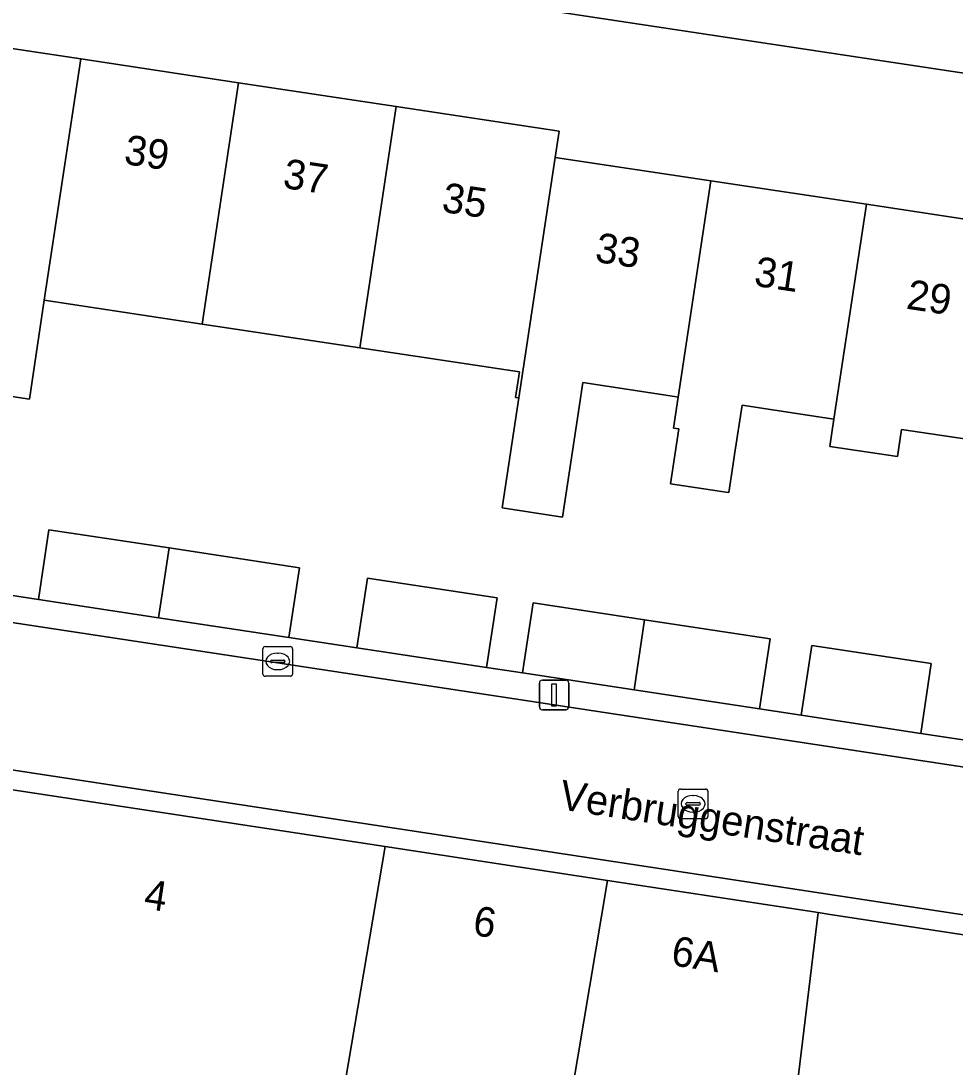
# Model space of a CAD drawing. Extents: x 163008 to 163854, y 382777 to 383982.
# Drawn here: x 163577.85 to 163609.33, y 383156.95 to 383192.22 of the extents above; entities that cross this region are included whole.
import ezdxf

# ---------------------------------------------------------------- set-up
doc = ezdxf.new("R2010")
doc.units = 0
for name, color, linetype in [('IMGEO_Erf', 7, 'Continuous'), ('IMGEO_Kolk', 7, 'Continuous'), ('IMGEO_Lichtmast', 7, 'Continuous'), ('IMGEO_Muur', 7, 'Continuous'), ('IMGEO_Openbare_ruimte_label', 7, 'Continuous'), ('IMGEO_Pand', 7, 'Continuous'), ('IMGEO_Pand_nummerreeks', 7, 'Continuous'), ('IMGEO_Rijbaan_lokaal_open', 7, 'Continuous'), ('IMGEO_Rioolput', 7, 'Continuous'), ('IMGEO_Voetpad_open', 7, 'Continuous')]:
    doc.layers.add(name, color=color, linetype=linetype)

msp = doc.modelspace()

# ---------------------------------------------------------------- linework, layer by layer
at = {"layer": 'IMGEO_Erf'}
for points in [[(163666.122, 383181.928), (163548.798, 383199.652), (163548.213, 383195.706), (163553.285, 383194.942), (163558.601, 383194.14), (163563.917, 383193.339), (163569.233, 383192.538), (163574.55, 383191.736), (163579.866, 383190.935), (163585.182, 383190.133), (163590.498, 383189.332), (163595.983, 383188.505), (163595.85, 383187.617), (163601.098, 383186.826), (163606.339, 383186.036), (163611.579, 383185.246)], [(163594.628, 383179.508), (163594.52, 383179.524), (163594.65, 383180.385), (163589.271, 383181.196), (163583.955, 383181.998), (163578.64, 383182.799), (163578.138, 383179.469), (163572.822, 383180.27), (163573.324, 383183.6), (163568.008, 383184.408), (163567.675, 383184.459), (163562.694, 383185.221), (163557.379, 383186.034), (163552.066, 383186.847), (163550.054, 383187.155), (163546.582, 383187.748), (163545.87, 383182.817), (163545.709, 383181.698), (163545.693, 383181.587)], [(163610.487, 383178.002), (163607.525, 383178.449), (163607.387, 383177.53), (163605.108, 383177.873), (163605.247, 383178.793), (163604.358, 383178.927), (163602.15, 383179.26), (163601.901, 383177.605), (163601.852, 383177.281), (163601.707, 383176.317), (163601.602, 383176.333), (163601.317, 383176.376), (163599.737, 383176.614), (163599.882, 383177.578), (163600.016, 383178.467), (163599.842, 383178.493), (163600, 383179.539), (163599.869, 383179.559), (163596.781, 383180.024), (163596.657, 383179.201), (163596.098, 383175.492), (163594.069, 383175.798), (163594.628, 383179.508)], [(163576.165, 383173.056), (163578.439, 383172.712), (163578.797, 383175.063), (163582.845, 383174.449), (163587.241, 383173.782), (163586.883, 383171.43), (163589.167, 383171.083), (163589.525, 383173.436), (163593.895, 383172.773), (163593.537, 383170.42), (163594.753, 383170.236), (163595.111, 383172.598), (163598.867, 383172.029), (163603.099, 383171.388), (163602.741, 383169.025), (163604.145, 383168.811), (163604.503, 383171.163), (163608.527, 383170.552), (163608.169, 383168.2), (163610.641, 383167.825)]]:
    msp.add_lwpolyline(points, dxfattribs=at)
at = {"layer": 'IMGEO_Kolk'}
for p, q in [((163586.005, 383170.201), (163586.005, 383171.053)), ((163586.08, 383171.127), (163586.932, 383171.127)), ((163586.493, 383170.907), (163586.518, 383170.907)), ((163587.006, 383171.053), (163587.006, 383170.201)), ((163586.264, 383170.621), (163586.264, 383170.633)), ((163586.702, 383170.584), (163586.304, 383170.584)), ((163586.307, 383170.67), (163586.705, 383170.67)), ((163586.748, 383170.633), (163586.748, 383170.621)), ((163586.932, 383170.127), (163586.08, 383170.127)), ((163586.516, 383170.347), (163586.491, 383170.347))]:
    msp.add_line(p, q, dxfattribs=at)
for points in [[(163586.005, 383170.201), (163586.005, 383171.053)], [(163586.08, 383171.127), (163586.932, 383171.127)], [(163587.006, 383171.053), (163587.006, 383170.201)], [(163586.932, 383170.127), (163586.08, 383170.127)]]:
    msp.add_lwpolyline(points, dxfattribs=at)
for centre, radius, start, end in [((163586.082, 383171.051), 0.0765, 91.552, 178.448), ((163586.082, 383171.051), 0.0765, 91.552, 178.448), ((163586.93, 383171.051), 0.0765, 1.552, 88.448), ((163586.93, 383171.051), 0.0765, 1.552, 88.448), ((163586.304, 383170.63), 0.0403, 85.8775, 175.7526), ((163586.301, 383170.62), 0.0366, 178.938, 274.7102), ((163586.705, 383170.627), 0.043, 264.8664, 352.4533), ((163586.709, 383170.632), 0.0386, 1.7309, 96.639), ((163586.082, 383170.203), 0.0765, 181.552, 268.448), ((163586.082, 383170.203), 0.0765, 181.552, 268.448), ((163586.93, 383170.203), 0.0765, 271.552, 358.448), ((163586.93, 383170.203), 0.0765, 271.552, 358.448)]:
    msp.add_arc(centre, radius, start, end, dxfattribs=at)
for centre, major_axis, ratio, start_param, end_param in [((163586.492, 383170.627), (-0.387, 0.002), 0.722429, 4.712389, 7.853982), ((163586.517, 383170.627), (-0.39, 0.002), 0.717154, 1.570796, 4.712389)]:
    msp.add_ellipse(centre, major_axis=major_axis, ratio=ratio, start_param=start_param, end_param=end_param, dxfattribs=at)
at = {"layer": 'IMGEO_Lichtmast'}
for p, q in [((163595.321, 383169.094), (163595.321, 383169.894)), ((163595.321, 383169.894), (163595.321, 383169.094)), ((163595.421, 383169.994), (163596.211, 383169.994)), ((163596.211, 383169.994), (163595.421, 383169.994)), ((163596.311, 383169.894), (163596.311, 383169.094)), ((163596.311, 383169.094), (163596.311, 383169.894)), ((163596.211, 383168.994), (163595.421, 383168.994)), ((163595.421, 383168.994), (163596.211, 383168.994))]:
    msp.add_line(p, q, dxfattribs=at)
msp.add_lwpolyline([(163595.741, 383169.869), (163595.891, 383169.869), (163595.891, 383169.119), (163595.741, 383169.119), (163595.741, 383169.869)], dxfattribs=at)
for centre, start, end in [((163595.421, 383169.894), 90, 180), ((163595.421, 383169.894), 90, 180), ((163596.211, 383169.894), 0, 90), ((163596.211, 383169.894), 360, 90), ((163595.421, 383169.094), 180, 270), ((163595.421, 383169.094), 180, 270), ((163596.211, 383169.094), 270, 0), ((163596.211, 383169.094), 270, 0)]:
    msp.add_arc(centre, 0.1, start, end, dxfattribs=at)
at = {"layer": 'IMGEO_Muur'}
msp.add_lwpolyline([(163590.125, 383164.381), (163604.715, 383162.158)], dxfattribs=at)
at = {"layer": 'IMGEO_Pand'}
for points in [[(163579.866, 383190.935), (163574.55, 383191.736), (163573.324, 383183.6), (163572.822, 383180.27), (163578.138, 383179.469), (163578.64, 383182.799)], [(163579.866, 383190.935), (163578.64, 383182.799), (163583.955, 383181.998), (163585.182, 383190.133)], [(163589.271, 383181.196), (163590.498, 383189.332), (163585.182, 383190.133), (163583.955, 383181.998)], [(163589.271, 383181.196), (163594.65, 383180.385), (163594.52, 383179.524), (163594.628, 383179.508), (163595.85, 383187.617), (163595.983, 383188.505), (163590.498, 383189.332)], [(163601.098, 383186.826), (163595.85, 383187.617), (163594.628, 383179.508), (163594.069, 383175.798), (163596.098, 383175.492), (163596.657, 383179.201), (163596.781, 383180.024), (163599.869, 383179.559), (163600, 383179.539)], [(163606.339, 383186.036), (163601.098, 383186.826), (163600, 383179.539), (163599.842, 383178.493), (163600.016, 383178.467), (163599.882, 383177.578), (163599.737, 383176.614), (163601.317, 383176.376), (163601.602, 383176.333), (163601.707, 383176.317), (163601.852, 383177.281), (163601.901, 383177.605), (163602.15, 383179.26), (163604.358, 383178.927), (163605.247, 383178.793)], [(163611.579, 383185.246), (163606.339, 383186.036), (163605.247, 383178.793), (163605.108, 383177.873), (163607.387, 383177.53), (163607.525, 383178.449), (163610.487, 383178.002)], [(163582.845, 383174.449), (163578.797, 383175.063), (163578.439, 383172.712), (163582.49, 383172.097)], [(163582.845, 383174.449), (163582.49, 383172.097), (163586.883, 383171.43), (163587.241, 383173.782)], [(163593.537, 383170.42), (163593.895, 383172.773), (163589.525, 383173.436), (163589.167, 383171.083)], [(163598.511, 383169.666), (163598.867, 383172.029), (163595.111, 383172.598), (163594.753, 383170.236)], [(163598.511, 383169.666), (163602.741, 383169.025), (163603.099, 383171.388), (163598.867, 383172.029)], [(163604.145, 383168.811), (163608.169, 383168.2), (163608.527, 383170.552), (163604.503, 383171.163)], [(163575.341, 383166.634), (163572.264, 383148.601), (163572.56, 383148.482), (163572.529, 383148.272), (163586.426, 383142.608), (163590.125, 383164.381)], [(163597.621, 383163.239), (163590.125, 383164.381), (163586.426, 383142.608), (163593.656, 383139.661)], [(163603.961, 383155.946), (163604.715, 383162.158), (163597.621, 383163.239), (163593.656, 383139.661), (163600.974, 383136.678), (163603.078, 383150.126)], [(163631.969, 383158.004), (163605.116, 383162.097), (163604.715, 383162.158), (163603.961, 383155.946), (163603.078, 383150.126), (163600.974, 383136.678), (163625.249, 383126.784)]]:
    msp.add_lwpolyline(points, close=True, dxfattribs=at)
at = {"layer": 'IMGEO_Rijbaan_lokaal_open'}
for points in [[(163542.236, 383172.265), (163567.427, 383168.507), (163651.335, 383155.72), (163658.206, 383154.673), (163658.136, 383154.035), (163663.431, 383153.242), (163667.475, 383152.649), (163671.164, 383176.895), (163671.375, 383178.333), (163671.627, 383180.045), (163667.228, 383180.698), (163666.553, 383176.284), (163664.116, 383160.362)], [(163662.219, 383159.074), (163547.368, 383176.527)]]:
    msp.add_lwpolyline(points, dxfattribs=at)
at = {"layer": 'IMGEO_Rioolput'}
for p, q in [((163600.001, 383165.398), (163600.001, 383166.25)), ((163600.076, 383166.324), (163600.928, 383166.324)), ((163601.002, 383166.25), (163601.002, 383165.398)), ((163600.303, 383165.867), (163600.701, 383165.867)), ((163600.489, 383166.104), (163600.514, 383166.104)), ((163600.26, 383165.818), (163600.26, 383165.83)), ((163600.698, 383165.781), (163600.3, 383165.781)), ((163600.512, 383165.544), (163600.487, 383165.544)), ((163600.744, 383165.83), (163600.744, 383165.818)), ((163600.928, 383165.324), (163600.076, 383165.324))]:
    msp.add_line(p, q, dxfattribs=at)
for points in [[(163600.001, 383165.398), (163600.001, 383166.25)], [(163600.076, 383166.324), (163600.928, 383166.324)], [(163601.002, 383166.25), (163601.002, 383165.398)], [(163600.928, 383165.324), (163600.076, 383165.324)]]:
    msp.add_lwpolyline(points, dxfattribs=at)
for centre, radius, start, end in [((163600.078, 383166.248), 0.0765, 91.552, 178.448), ((163600.078, 383166.248), 0.0765, 91.552, 178.448), ((163600.926, 383166.248), 0.0765, 1.552, 88.448), ((163600.926, 383166.248), 0.0765, 1.552, 88.448), ((163600.3, 383165.827), 0.0403, 85.8775, 175.7526), ((163600.705, 383165.829), 0.0386, 1.7309, 96.639), ((163600.297, 383165.817), 0.0366, 178.938, 274.7102), ((163600.701, 383165.824), 0.043, 264.8664, 352.4533), ((163600.078, 383165.4), 0.0765, 181.552, 268.448), ((163600.078, 383165.4), 0.0765, 181.552, 268.448), ((163600.926, 383165.4), 0.0765, 271.552, 358.448), ((163600.926, 383165.4), 0.0765, 271.552, 358.448)]:
    msp.add_arc(centre, radius, start, end, dxfattribs=at)
for centre, major_axis, ratio, start_param, end_param in [((163600.488, 383165.824), (-0.387, 0.002), 0.722429, 4.712389, 7.853982), ((163600.513, 383165.824), (-0.39, 0.002), 0.717154, 1.570796, 4.712389)]:
    msp.add_ellipse(centre, major_axis=major_axis, ratio=ratio, start_param=start_param, end_param=end_param, dxfattribs=at)
at = {"layer": 'IMGEO_Voetpad_open'}
for points in [[(163546.356, 383200.021), (163548.798, 383199.652), (163666.122, 383181.928), (163667.379, 383181.747), (163668.321, 383188.294)], [(163610.641, 383167.825), (163608.169, 383168.2), (163604.145, 383168.811), (163602.741, 383169.025), (163598.511, 383169.666), (163594.753, 383170.236), (163593.537, 383170.42), (163589.167, 383171.083), (163586.883, 383171.43), (163582.49, 383172.097), (163578.439, 383172.712), (163576.165, 383173.056), (163571.836, 383173.713), (163567.712, 383174.339), (163565.409, 383174.688), (163561.181, 383175.33), (163556.975, 383175.968), (163554.681, 383176.317), (163550.526, 383176.947), (163546.258, 383177.595), (163545.615, 383177.956), (163542.791, 383181.541), (163542.503, 383179.637), (163543.527, 383178.267)], [(163545.77, 383176.763), (163547.368, 383176.527), (163662.219, 383159.074)]]:
    msp.add_lwpolyline(points, dxfattribs=at)
msp.add_lwpolyline([(163567.427, 383168.507), (163567.317, 383167.857), (163575.341, 383166.634), (163590.125, 383164.381), (163597.621, 383163.239), (163604.715, 383162.158), (163605.116, 383162.097), (163631.969, 383158.004), (163645.335, 383155.967), (163651.236, 383155.068), (163651.335, 383155.72)], close=True, dxfattribs=at)

# ---------------------------------------------------------------- texts
at = {"layer": 'IMGEO_Openbare_ruimte_label'}
msp.add_text('Verbruggenstraat', height=1, rotation=351.3191, dxfattribs=at).set_placement((163595.955, 383165.648))
at = {"layer": 'IMGEO_Pand_nummerreeks'}
for s, rotation, p in [('39', 351.4271, (163581.292, 383187.402)), ('37', 351.4271, (163586.646, 383186.595)), ('35', 351.4271, (163592, 383185.788)), ('33', 351.4286, (163597.166, 383184.102)), ('31', 351.4286, (163602.521, 383183.295)), ('29', 351.4286, (163607.652, 383182.521)), ('4', 351.4164, (163581.964, 383162.3)), ('6', 351.1363, (163593.042, 383161.409)), ('6A', 351.1363, (163599.725, 383160.392))]:
    msp.add_text(s, height=1, rotation=rotation, dxfattribs=at).set_placement(p)

doc.saveas('drawing.dxf')
